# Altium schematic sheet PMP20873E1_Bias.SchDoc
size 431 x 279 mm; Date: Not shown in title block; ApprovedBy: Not shown in title block; CheckedBy: Not shown in title block; Author: Not shown in title block; CompanyName: Not shown in title block; DrawnBy: Eric Faraci; Engineer: Not shown in title block; Organization: Not shown in title block; Address1: Not shown in title block; Address2: Not shown in title block; Address3: Not shown in title block; Address4: Not shown in title block; DocumentNumber: 1; Revision: Use project parameter SCH_Rev; SheetNumber: 1; SheetTotal: 1; PageSetup: Record=PageOptions¦CenterHorizontal=True¦CenterVertical=True¦PrintScale=0.64¦XCorrection=1.00¦YCorrection=1.00¦PrintKind=0¦BorderSize=5000000¦LeftOffset=0¦BottomOffset=0¦Orientation=2¦PaperLength=1000¦PaperWidth=1000¦Scale=100¦PaperSource=15¦PrintQuality=600¦MediaType=1¦DitherType=10¦PaperKind=Letter¦PrintScaleMode=1
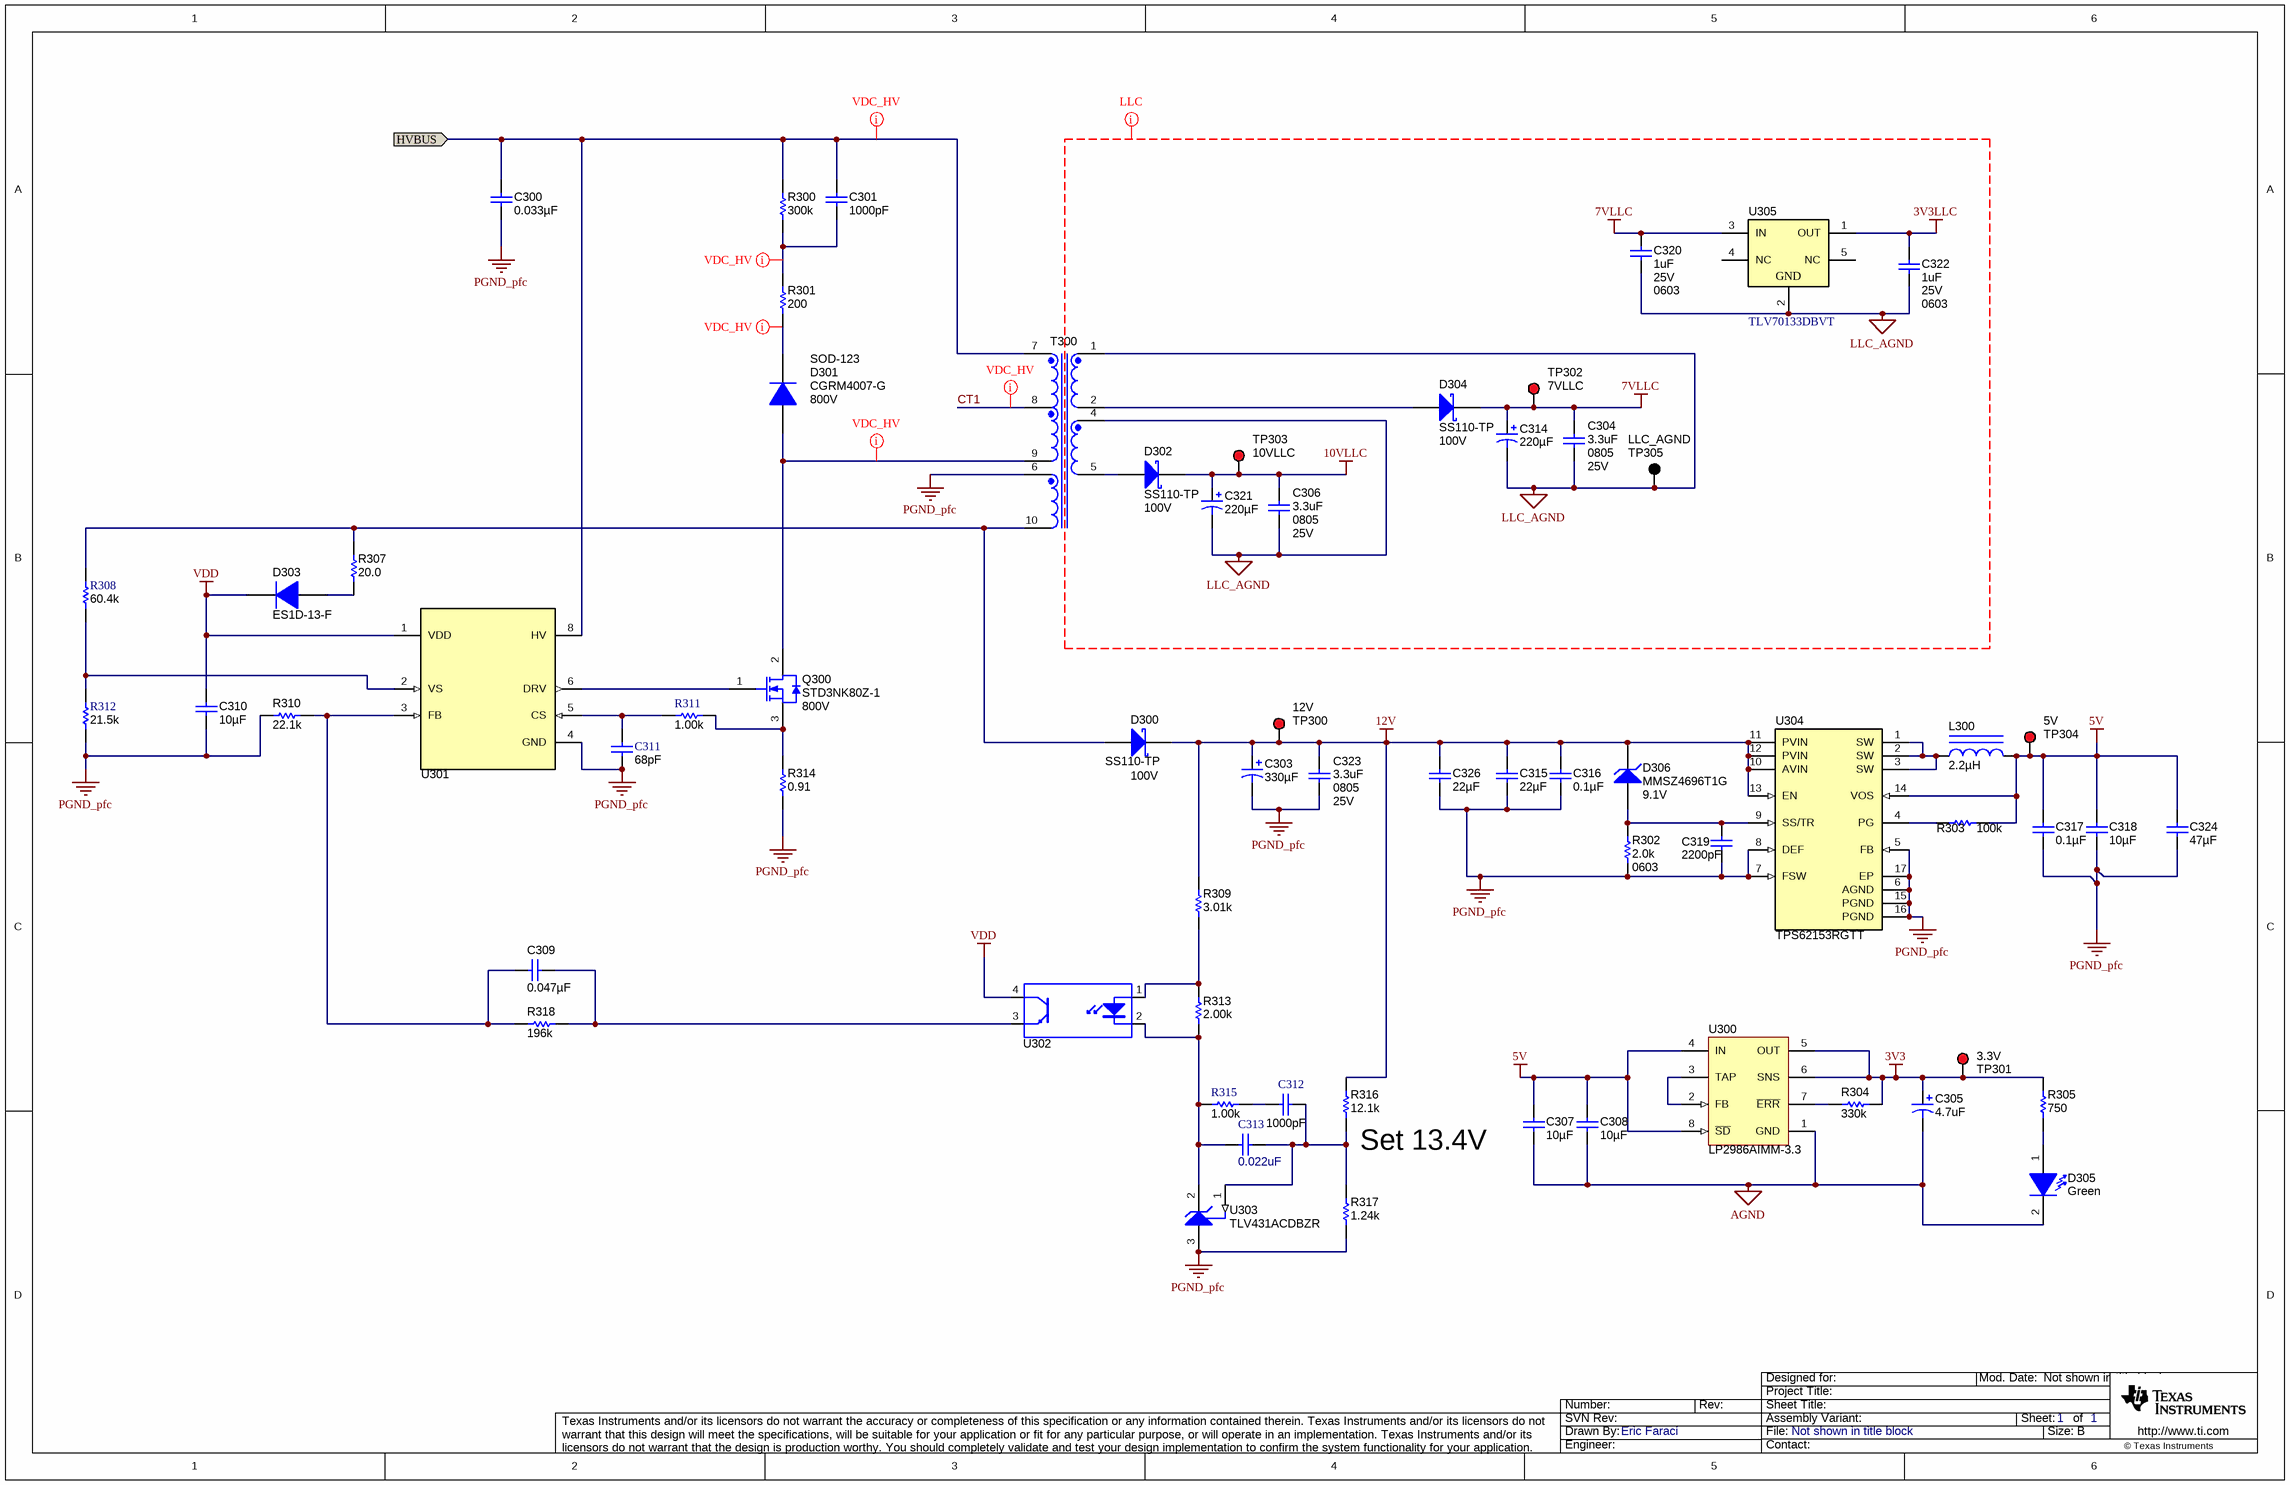
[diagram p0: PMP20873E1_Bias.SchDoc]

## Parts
C300  ValueDisplayed: 0.033µF  [1210]  (hidden comment: GRM32DR72J333KW01L)
C301  ValueDisplayed: 1000pF  [0805_HV]  (hidden comment: C2012X7R2E102K)
C303  ValueDisplayed: 330µF  [ZL_1000x1250]  (hidden comment: 25ZL330MEFC10X12.5)
C304  ValueDisplayed: 3.3uF  PackageReference: 0805  Value2: 25V  [0805_HV]  (hidden comment: GRM21BR71E335KA73L)
C305  ValueDisplayed: 4.7uF  [3528-21]  (hidden comment: 293D475X9010B2TE3)
C306  ValueDisplayed: 3.3uF  PackageReference: 0805  Value2: 25V  [0805_HV]  (hidden comment: GRM21BR71E335KA73L)
C307  ValueDisplayed: 10µF  [0805_HV]  (hidden comment: C0805C106K8PACTU)
C308  ValueDisplayed: 10µF  [0805_HV]  (hidden comment: C0805C106K8PACTU)
C309  ValueDisplayed: 0.047µF  [0805_HV]  (hidden comment: C0805C473K5RACTU)
C310  ValueDisplayed: 10µF  [1206]  (hidden comment: GRM31CR71E106KA12L)
C311  ValueDisplayed: 68pF  [0603]  (hidden comment: 06035A680JAT2A)
C312  ValueDisplayed: 1000pF  [0603]  (hidden comment: 06035A102KAT2A)
C313  ValueDisplayed: 0.022uF  [0603]  (hidden comment: C0603C223K3RACTU)
C314  ValueDisplayed: 220µF  [7361-38]  (hidden comment: TPSV227K016R0050)
C315  ValueDisplayed: 22µF  [1206]  (hidden comment: 1206YD226MAT2A)
C316  ValueDisplayed: 0.1µF  [0402]  (hidden comment: C1005X7R1H104K)
C317  ValueDisplayed: 0.1µF  [0402]  (hidden comment: C1005X7R1H104K)
C318  ValueDisplayed: 10µF  [0805_HV]  (hidden comment: GRM21BR71A106KE51L)
C319  ValueDisplayed: 2200pF  [0402]  (hidden comment: GRM155R71E222KA01D)
C320  ValueDisplayed: 1uF  Value2: 25V  [0603]  (hidden comment: C1608X7R1E105K080AB)
C321  ValueDisplayed: 220µF  [7361-38]  (hidden comment: TPSV227K016R0050)
C322  ValueDisplayed: 1uF  Value2: 25V  [0603]  (hidden comment: C1608X7R1E105K080AB)
C323  ValueDisplayed: 3.3uF  PackageReference: 0805  Value2: 25V  [0805_HV]  (hidden comment: GRM21BR71E335KA73L)
C324  ValueDisplayed: 47µF  [1210]  (hidden comment: 12106D476MAT2A)
C326  ValueDisplayed: 22µF  [1206]  (hidden comment: 1206YD226MAT2A)
D300  SS110-TP  value 100V  [SMA]
D301  CGRM4007-G  Value2: 800V  [SOD-123]
D302  SS110-TP  value 100V  [SMA]
D303  ES1D-13-F  [SMA]
D304  SS110-TP  value 100V  [SMA]
D305  value Green  [LG L29K_GREEN]  (hidden comment: LG L29K-G2J1-24-Z)
D306  MMSZ4696T1G  value 9.1V  [SOD-123]
L300  ValueDisplayed: 2.2µH  [SDR0403]  (hidden comment: SDR0403-2R2ML)
Q300  STD3NK80Z-1  value 800V  [IPAK]
R300  ValueDisplayed: 300k  [1206]  (hidden comment: RC1206FR-07300KL)
R301  ValueDisplayed: 200  [0805_HV]  (hidden comment: ERJ-6GEYJ201V)
R302  value 2.0k  [0603]  (hidden comment: CRCW06032K00JNEA)
R303  value 100k  [0402]  (hidden comment: CRCW0402100KFKED)
R304  ValueDisplayed: 330k  [0603]  (hidden comment: RG1608P-334-B-T5)
R305  ValueDisplayed: 750  [0603]  (hidden comment: RT0603DRE07750RL)
R307  ValueDisplayed: 20.0  [0603]  (hidden comment: RC0603FR-0720RL)
R308  value 60.4k  [0603]  (hidden comment: CRCW060360K4FKEA)
R309  ValueDisplayed: 3.01k  [0805_HV]  (hidden comment: CRCW08053K01FKEA)
R310  ValueDisplayed: 22.1k  [0805_HV]  (hidden comment: CRCW080522K1FKEA)
R311  value 1.00k  [0603]  (hidden comment: CRCW06031K00FKEA)
R312  value 21.5k  [0603]  (hidden comment: CRCW060321K5FKEA)
R313  ValueDisplayed: 2.00k  [0805_HV]  (hidden comment: CRCW08052K00FKEA)
R314  ValueDisplayed: 0.91  [0805_HV]  (hidden comment: CRM0805-FX-R910ELF)
R315  value 1.00k  [0603]  (hidden comment: CRCW06031K00FKEA)
R316  ValueDisplayed: 12.1k  [0805_HV]  (hidden comment: CRCW080512K1FKEA)
R317  ValueDisplayed: 1.24k  [0805_HV]  (hidden comment: CRCW08051K24FKEA)
R318  ValueDisplayed: 196k  [0805_HV]  (hidden comment: ERJ-6ENF1963V)
T300  750315894  [Wurth_750315894]  (value not drawn)
TP300  12V  [Keystone5000]
TP301  3.3V  [Keystone5000]
TP302  7VLLC  [Keystone5000]
TP303  10VLLC  [Keystone5000]
TP304  5V  [Keystone5000]
TP305  LLC_AGND  [Keystone5001]
U300  LP2986AIMM-3.3  [MUA08A_N]
U301  UCC28740DR  [D0007A_N]  (value not drawn)
U302  LTV-817S  [DIP254P762X350-4]  (value not drawn)
U303  TLV431ACDBZR  [DBZ0003A_N]
U304  TPS62153RGTT  [RGT0016C]
U305  TLV70133DBVT  [DBV0005A_N]

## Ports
HVBUS

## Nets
3V3: C305.1(+) R304.2 R305.2 TP301.1 U300.5(OUT) U300.6(SNS)
3V3LLC: C322.2 U305.1(OUT)
5V: C307.1 C308.1 C317.1 C318.2 C324.1 L300.2 R303.2 TP304.1 U300.4(IN) U300.8(~{SD}) U304.14(VOS)
7VLLC: C304.1 C314.1(+) C320.2 D304.1(K) TP302.1 U305.3(IN)
10VLLC: C306.1 C321.1(+) D302.1(K) TP303.1
12V: C303.1(+) C315.1 C316.1 C323.1 C326.1 D300.1(K) D306.1(K) R309.2 R316.2 TP300.1 U304.10(AVIN) U304.11(PVIN) U304.12(PVIN) U304.13(EN)
AGND: C305.2(-) C307.2 C308.2 D305.2(K) U300.1(GND)
LLC_AGND: C304.2 C306.2 C314.2(-) C320.1 C321.2(-) C322.1 T300.1 T300.4 TP305.1 U305.2(GND)
PGND_pfc: C300.2 C303.2(-) C310.2 C311.2 C315.2 C316.2 C317.2 C318.1 C319.2 C323.2 C324.2 C326.2 R302.2 R310.1 R312.1 R314.1 R317.1 T300.6 U301.4(GND) U303.3(ANODE) U304.5(FB) U304.6(AGND) U304.7(FSW) U304.8(DEF) U304.15(PGND) U304.16(PGND) U304.17(EP)
VDD: C310.1 D303.1(K) U301.1(VDD) U302.4(C)
CT1: T300.8
HVBUS: C300.1 C301.1 R300.2 T300.7 U301.8(HV) ; port HVBUS
NetC301_2: C301.2 R300.1 R301.2
NetC309_1: C309.1 R318.2 U302.3(E)
NetC309_2: C309.2 R310.2 R318.1 U301.3(FB)
NetC311_1: C311.1 R311.1 U301.5(CS)
NetC312_1: C312.1 C313.1 R316.1 R317.2 U303.1(REF)
NetC312_2: C312.2 R315.2
NetC313_2: C313.2 R313.1 R315.1 U302.2(K) U303.2(CATHODE)
NetC319_1: C319.1 D306.2(A) R302.1 U304.9(SS/TR)
NetD300_2: D300.2(A) R307.2 R308.2 T300.10
NetD301_1: D301.1(K) R301.1
NetD301_2: D301.2(A) Q300.2(D) T300.9
NetD302_2: D302.2(A) T300.5
NetD303_2: D303.2(A) R307.1
NetD304_2: D304.2(A) T300.2
NetD305_1: D305.1(A) R305.1
NetL300_1: L300.1 U304.1(SW) U304.2(SW) U304.3(SW)
NetQ300_1: Q300.1(G) U301.6(DRV)
NetQ300_3: Q300.3(S) R311.2 R314.2
NetR303_1: R303.1 U304.4(PG)
NetR304_1: R304.1 U300.7(~{ERR})
NetR308_1: R308.1 R312.2 U301.2(VS)
NetR309_1: R309.1 R313.2 U302.1(A)
NetU300_2: U300.2(FB) U300.3(TAP)

Not connected (* = marked no-connect by the designer): U305 4(NC) 5(NC)

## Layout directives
net class VDC_HV: CT1, HVBUS, NetC301_2, NetD301_1, NetD301_2
net class LLC: 3V3LLC, 7VLLC, 10VLLC, LLC_AGND

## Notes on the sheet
- (near R316) Set 13.4V

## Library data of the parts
C300 = GRM32DR72J333KW01L: CAP, CERM, 0.033 µF, 630 V, +/- 10%, X7R, 1210; Manufacturer: MuRata; Polarized: N; CompType: Capacitor; Value: 0.033uF; U/M: EA; Cap_F: 0.000000033; Tolerance_%: 10; Value1: Unknown; VDC_V: 630; Value2: 630V; TaMin_C: -55; TaMax_C: 125; AEC Category: Q200
C301 = C2012X7R2E102K: CAP, CERM, 1000 pF, 250 V, +/- 10%, X7R, 0805; Manufacturer: TDK; Polarized: N; CompType: Capacitor; Value: 1000pF; U/M: EA; Cap_F: 0.000000001; Tolerance_%: 10; ESR_ohm: 0.2815; Value1: 0.2815 ohm; VDC_V: 250; Value2: 250V; TaMin_C: -55; TaMax_C: 125; Cap_Case: 0805; AEC Category: Q200
C303 = 25ZL330MEFC10X12.5: CAP, AL, 330 µF, 25 V, +/- 20%, 0.053 ohm, TH; Manufacturer: Rubycon; Polarized: Y; CompType: Capacitor; Value: 330uF; U/M: EA; Cap_F: 0.00033; Tolerance_%: 20; VDC_V: 25; Value2: 25V; ESR_ohm: 0.053; IRMS_A: 1.03; TaMin_C: -40; TaMax_C: 105; Cap_Case: 10x12.5mm
C304 C306 C323 = GRM21BR71E335KA73L: CAP, CERM, 3.3uF, 25V, +/-10%, X7R, 0805; Manufacturer: MuRata; Polarized: N; CompType: Capacitor; U/M: EA; Cap_F: 0.0000033; Tolerance_%: 10; Value1: Unknown; VDC_V: 25; TaMin_C: -55; TaMax_C: 125
C305 = 293D475X9010B2TE3: CAP, TA, 4.7uF, 10V, +/-10%, 3.4 ohm, SMD; Manufacturer: Vishay-Sprague; Polarized: Y; CompType: Capacitor; U/M: EA; Cap_F: 0.0000047; Tolerance_%: 10; Value1: 3.4 ohm; ESR_Ohm: 3.4; IRMS_A: 0.16; TaMin_C: -55; TaMax_C: 125; Cap_Case: B
C307 C308 = C0805C106K8PACTU: CAP, CERM, 10 µF, 10 V, +/- 10%, X5R, 0805; Manufacturer: Kemet; Polarized: N; CompType: Capacitor; Value: 10uF; U/M: EA; Cap_F: 0.00001; Tolerance_%: 10; ESR_ohm: 0.003; Value1: 0.003 ohm; Value2: 10V; IRMS_A: 11.43; TaMin_C: -55; TaMax_C: 85; Cap_Case: 0805
C309 = C0805C473K5RACTU: CAP, CERM, 0.047 µF, 50 V, +/- 10%, X7R, 0805; Manufacturer: Kemet; Polarized: N; CompType: Capacitor; Value: 0.047uF; U/M: EA; Cap_F: 0.000000047; Tolerance_%: 10; ESR_ohm: 0.088; Value1: 0.088 ohm; VDC_V: 50; Value2: 50V; IRMS_A: 1.04; TaMin_C: -55; TaMax_C: 125; Cap_Case: 0805; AEC Category: Q200
C310 = GRM31CR71E106KA12L: CAP, CERM, 10 µF, 25 V, +/- 10%, X7R, 1206; Manufacturer: MuRata; Polarized: N; CompType: Capacitor; Value: 10uF; U/M: EA; Cap_F: 0.00001; Tolerance_%: 10; Value1: Unknown; VDC_V: 25; Value2: 25V; TaMin_C: -55; TaMax_C: 125; Cap_Case: 2220; AEC Category: Q200
C311 = 06035A680JAT2A: CAP, CERM, 68pF, 50V, +/-5%, C0G/NP0, 0603; Manufacturer: AVX; Polarized: N; CompType: Capacitor; U/M: EA; Cap_F: 0.000000000068; Tolerance_%: 5; ESR_Ohm: 0.144; Value1: 0.144 ohm; VDC_V: 50; TaMin_C: -55; TaMax_C: 125
C312 = 06035A102KAT2A: CAP, CERM, 1000pF, 50V, +/-10%, C0G/NP0, 0603; Manufacturer: AVX; Polarized: N; CompType: Capacitor; U/M: EA; Cap_F: 0.000000001; Tolerance_%: 10; ESR_Ohm: 0.048; Value1: 0.048 ohm; VDC_V: 50; TaMin_C: -55; TaMax_C: 125
C313 = C0603C223K3RACTU: CAP, CERM, 0.022uF, 25V, +/-10%, X7R, 0603; Manufacturer: Kemet; Polarized: N; CompType: Capacitor; U/M: EA; Cap_F: 0.000000022; Tolerance_%: 10; Value1: Unknown; VDC_V: 25; TaMin_C: -55; TaMax_C: 125
C314 C321 = TPSV227K016R0050: CAP, TA, 220 µF, 16 V, +/- 10%, 0.05 ohm, SMD; Manufacturer: AVX; Polarized: Y; CompType: Capacitor; Value: 220uF; U/M: EA; Cap_F: 0.00022; Tolerance_%: 10; VDC_V: 16; Value2: 16V; ESR_ohm: 0.05; IRMS_A: 2.012; TaMin_C: -55; TaMax_C: 125
C315 C326 = 1206YD226MAT2A: CAP, CERM, 22 µF, 16 V, +/- 20%, X5R, 1206; Manufacturer: AVX; Polarized: N; CompType: Capacitor; Value: 22uF; U/M: EA; Cap_F: 0.000022; Tolerance_%: 20; Value1: Unknown; VDC_V: 16; Value2: 16V; TaMin_C: -55; TaMax_C: 85; AEC Category: Q200
C316 C317 = C1005X7R1H104K: CAP, CERM, 0.1uF, 50V, +/-10%, C0G/NP0, 0402; Manufacturer: TDK; Polarized: N; CompType: Capacitor; U/M: EA; Cap_F: 0.0000001; Tolerance_%: 10; VDC_V: 50; TaMin_C: -55; TaMax_C: 125
C318 = GRM21BR71A106KE51L: CAP, CERM, 10uF, 10V, +/-10%, X7R, 0805; Manufacturer: MuRata; Polarized: N; CompType: Capacitor; U/M: EA; Cap_F: 0.00001; Tolerance_%: 10; ESR_Ohm: 0.003; Value1: 0.003 ohm; TaMin_C: -55; TaMax_C: 125; Cap_Case: 0805
C319 = GRM155R71E222KA01D: CAP, CERM, 2200pF, 25V, +10/%, X7R, 0402; Manufacturer: MuRata; Polarized: N; CompType: Capacitor; U/M: EA; Cap_F: 0.0000000022; Tolerance_%: 10; Value1: Unknown; VDC_V: 25; TaMin_C: -55; TaMax_C: 125
C320 C322 = C1608X7R1E105K080AB: CAP, CERM, 1uF, 25V, +/-10%, X7R, 0603; Manufacturer: TDK; Polarized: N; CompType: Capacitor; U/M: EA; Cap_F: 0.000001; Tolerance_%: 10; Value1: Unknown; VDC_V: 25; TaMin_C: -55; TaMax_C: 125
C324 = 12106D476MAT2A: CAP, CERM, 47 µF, 6.3 V, +/- 20%, X5R, 1210; Manufacturer: AVX; Polarized: N; CompType: Capacitor; Value: 47uF; U/M: EA; Cap_F: 0.000047; Tolerance_%: 20; Value1: Unknown; VDC_V: 6.3; Value2: 6.3V; TaMin_C: -55; TaMax_C: 85; AEC Category: Q200
D300 D302 D304 = 10BQ100TRPBF: Diode, Schottky, 100V, 1A, SMB; Manufacturer: International Rectifier; U/M: EA; Vf_V: 0.78; Value2: 0.78V; Io_A: 1; Vr_V: 100; TJmax_C: 175; RJC_CperW: 36
D301 = US1M-13-F: Diode, Ultrafast, 800V, 1A, SMA; Manufacturer: Diodes Inc.; Value: 1.7V; U/M: EA; Vf_V: 1.7; Io_A: 1; Vr_V: 800; TJmax_C: 150; RJC_CperW: 30
D303 = ES1D-13-F: Diode, Ultrafast, 200 V, 1 A, SMA; Manufacturer: Diodes Inc.; U/M: EA; Vf_V: 0.92; Value: 200V; Value1: 1A; Value2: 0.92V; Io_A: 1; Vr_V: 200; TJmax_C: 150; RJC_CperW: 25; AEC Category: Q101
D305 = LG L29K-G2J1-24-Z: LED, Green, SMD; Manufacturer: OSRAM; Vf_V: 1.7; Value2: 1.7V; Io_A: 0.002; Tjmax_C: 110; Value1: W; U/M: EA
D306 = MMSZ4696T1G: Diode, Zener, 9.1 V, 500 mW, SOD-123; Manufacturer: ON Semiconductor; SymbolCreator: a0412235; U/M: EA; Power_W: 0.5; Vz_V: 9.1; Value1: 0.5W; RJA_CperW: 340; AEC Category: Q101
L300 = SDR0403-2R2ML: Inductor, Drum Core, Ferrite, 2.2 µH, 2.6 A, 0.047 ohm, SMD; Manufacturer: Bourns; Value: 2.2uH; Ind_H: 2.2E-6; Imax_A: 2.6; Irms: 2.6A @ 40C rise; Isat: 3.77A @ 10% inductance drop; DCR_ohm: 0.047; Value2: 2.6A; AEC Category: Q200
Q300 = STD3NK80Z-1: MOSFET, N-CH, 800V, 2.5A, IPAK; Manufacturer: ST Microelectronics; Alternate Manufacturer: None; U/M: EA; ChType: N; VdsMax_V: 800; Value1: 4.5 ohm; Rdson45_Ohm: 4.5; Value2: 19 nC; QgTyp_nC: 19; Vgs_V: 30; IdsMax_A: 2.5
R300 = RC1206FR-07300KL: RES, 300 k, 1%, 0.25 W, 1206; Manufacturer: Yageo America; CompType: Resistor; Value: 300k; Res_ohm: 300000; Tolerance_%: 1; Power_W: 0.25; Value2: 0.25W; VDC_V: 200; TempCo: 100 ppm/C; U/M: EA; AEC Category: Q200
R301 = ERJ-6GEYJ201V: RES, 200, 5%, 0.125 W, 0805; Manufacturer: Panasonic; CompType: Resistor; Value: 200; Value_Code: 200R; Tolerance_%: 5; Power_W: 0.125; Value2: 0.125W; VDC_V: 150; TempCo: 200 ppm/C; EIA_Code: E24; U/M: EA; AEC Category: Q200
R302 = CRCW06032K00JNEA: RES, 2.0k ohm, 5%, 0.1W, 0603; Manufacturer: Vishay-Dale; CompType: Resistor; Res_ohm: 2000; Value_Code: 2k00; Tolerance_%: 5; Power_W: 0.1; VDC_V: 75; TempCo: 200 ppm/C; EIA_Code: E24; U/M: EA
R303 = CRCW0402100KFKED: RES, 100k ohm, 1%, 0.063W, 0402; Manufacturer: Vishay-Dale; Alternate PartNumber: Equivalent; Alternate Manufacturer: Any; CompType: Resistor; Res_ohm: 100000; Tolerance_%: 1; Power_W: 0.063; VDC_V: 50; TempCo: 100 ppm/C; EIA_Code: E96; U/M: EA
R304 = RG1608P-334-B-T5: RES, 330 k, 0.1%, 0.1 W, 0603; Manufacturer: Susumu Co Ltd; CompType: Resistor; Value: 330k; Res_ohm: 330000; Tolerance_%: 0.1; Value2: 0.1W; VDC_V: 75; TempCo: 25 ppm/C; U/M: EA; AEC Category: Q200
R305 = RT0603DRE07750RL: RES, 750, 0.5%, 0.1 W, 0603; Manufacturer: Yageo America; CompType: Resistor; Value: 750; Value_Code: 750R; Tolerance_%: 0.5; Power_W: 0.1; Value2: 0.1W; VDC_V: 75; TempCo: 50 ppm/C; EIA_Code: E192; U/M: EA; AEC Category: Q200
R307 = RC0603FR-0720RL: RES, 20.0, 1%, 0.1 W, 0603; Manufacturer: Yageo America; CompType: Resistor; Value: 20.0; Res_ohm: 20; Value_Code: 20R0; Tolerance_%: 1; Power_W: 0.1; Value2: 0.1W; VDC_V: 150; TempCo: 200 ppm/C; EIA_Code: E96; U/M: EA; AEC Category: Q200
R308 = CRCW060360K4FKEA: RES, 60.4k ohm, 1%, 0.1W, 0603; Manufacturer: Vishay-Dale; CompType: Resistor; Res_ohm: 60400; Value_Code: 60k4; Tolerance_%: 1; Power_W: 0.1; VDC_V: 75; TempCo: 100 ppm/C; EIA_Code: E96; U/M: EA
R309 = CRCW08053K01FKEA: RES, 3.01 k, 1%, 0.125 W, 0805; Manufacturer: Vishay-Dale; CompType: Resistor; Value: 3.01k; Res_ohm: 3010; Value_Code: 3k01; Tolerance_%: 1; Power_W: 0.125; Value2: 0.125W; VDC_V: 150; TempCo: 100 ppm/C; EIA_Code: E96; U/M: EA
R310 = CRCW080522K1FKEA: RES, 22.1 k, 1%, 0.125 W, 0805; Manufacturer: Vishay-Dale; CompType: Resistor; Value: 22.1k; Res_ohm: 22100; Value_Code: 22k1; Tolerance_%: 1; Power_W: 0.125; Value2: 0.125W; VDC_V: 150; TempCo: 100 ppm/C; EIA_Code: E96; U/M: EA
R311 R315 = CRCW06031K00FKEA: RES, 1.00k ohm, 1%, 0.1W, 0603; Manufacturer: Vishay-Dale; CompType: Resistor; Res_ohm: 1000; Value_Code: 1k00; Tolerance_%: 1; Power_W: 0.1; VDC_V: 75; TempCo: 100 ppm/C; EIA_Code: E96; U/M: EA
R312 = CRCW060321K5FKEA: RES, 21.5k ohm, 1%, 0.1W, 0603; Manufacturer: Vishay-Dale; CompType: Resistor; Res_ohm: 21500; Value_Code: 21k5; Tolerance_%: 1; Power_W: 0.1; VDC_V: 75; TempCo: 100 ppm/C; EIA_Code: E96; U/M: EA
R313 = CRCW08052K00FKEA: RES, 2.00 k, 1%, 0.125 W, 0805; Manufacturer: Vishay-Dale; CompType: Resistor; Value: 2.00k; Res_ohm: 2000; Value_Code: 2k00; Tolerance_%: 1; Power_W: 0.125; Value2: 0.125W; VDC_V: 150; TempCo: 100 ppm/C; EIA_Code: E96; U/M: EA
R314 = CRM0805-FX-R910ELF: RES, 0.91, 1%, 0.25 W, 0805; Manufacturer: Bourns; CompType: Resistor; Value: 0.91; Value_Code: R910; Tolerance_%: 1; Power_W: 0.25; Value2: 0.25W; VDC_V: 0; TempCo: 100 ppm/C; EIA_Code: E96; U/M: EA; AEC Category: Q200
R316 = CRCW080512K1FKEA: RES, 12.1 k, 1%, 0.125 W, 0805; Manufacturer: Vishay-Dale; CompType: Resistor; Value: 12.1k; Res_ohm: 12100; Value_Code: 12k1; Tolerance_%: 1; Power_W: 0.125; Value2: 0.125W; VDC_V: 150; TempCo: 100 ppm/C; EIA_Code: E96; U/M: EA; AEC Category: Q200
R317 = CRCW08051K24FKEA: RES, 1.24 k, 1%, 0.125 W, 0805; Manufacturer: Vishay-Dale; CompType: Resistor; Value: 1.24k; Res_ohm: 1240; Value_Code: 1k24; Tolerance_%: 1; Power_W: 0.125; Value2: 0.125W; VDC_V: 150; TempCo: 100 ppm/C; EIA_Code: E96; U/M: EA
R318 = ERJ-6ENF1963V: RES, 196 k, 1%, 0.125 W, 0805; Manufacturer: Panasonic; CompType: Resistor; Value: 196k; Res_ohm: 196000; Tolerance_%: 1; Power_W: 0.125; Value2: 0.125W; TempCo: 100 ppm/C; EIA_Code: E96; U/M: EA; AEC Category: Q200
T300 = 750315894: Transformer, 13 mH, TH; Manufacturer: Wurth Elektronik; SymbolCreator: Altium; Lp: 13000; DCR_ohm: 20.9; LeakageL: 200; Ns1toNp: 0.042; Ns2toNp: 0.035; Rs1: 0.045; Rs2: 0.4
TP300-TP304 = 5000: Test Point, Miniature, Red, TH; Manufacturer: Keystone; CompType: Test Point Loop; U/M: EA
TP305 = 5001: Test Point, Miniature, Black, TH; Manufacturer: Keystone; CompType: Test Point Loop; U/M: EA
U300 = LP2986AIMM-3.3: Micropower, 200 mA Ultra Low-Dropout Fixed or Adjustable Voltage Regulator, 8-pin Mini SOIC; Manufacturer: National Semiconductor; PackageTopMarking: ZXTT*L40A; PowerWise: N; CompType: LDO IC
U301 = UCC28740DR: Constant-Voltage, Constant-Current Flyback Controller Using Opto-Coupler Feedback, D0007A; Manufacturer: Texas Instruments; SymbolCreator: a0412235; CompType: IC; U/M: EA
U302 = LTV-817S: Optocoupler, 5 kV, 50-600% CTR, TH-4; Manufacturer: Lite-On; CTR_Min: 50% @ 5mA; CTR_Max: 600% @ 5mA; Voltage_Isolation_Vrms: 5000; tr_typ: 4us; tf_typ: 3us; U/M: EA
U303 = TLV431ACDBZR: Low Voltage Adjustable Precision Shunt Regulator, 39 ppm / degC, 15 mA, 0 to 70 degC, 3-pin SOT-23 (DBZ), Green (RoHS & no Sb/Br); Manufacturer: Texas Instruments; Alternate PartNumber: Equivalent; Iout/Iz(Max)(mA): 15; Min Iz for Regulation(uA): 80; Rating: Catalog; SubFamily: Shunt Voltage Reference; Temp Coeff(Max)(ppm/ degree C): 129; Temp Coeff(Typ)(ppm/ degree C): 39; VO Adj(Max)(V): 6; VO Adj(Min)(V): 1.24
U304 = TPS62153RGTT: Buck Step Down Regulator with 3 to 17 V Input and 5 V Output, -40 to 85 degC, 16-Pin QFN (RGT), Green (RoHS & no Sb/Br); Manufacturer: Texas Instruments; Alternate PartNumber: Equivalent; Duty Cycle(Max)(%): 100; Iout(Max)(A): 1; Iq(Typ)(mA): 0.017; Preset Vout(V): 5; Rating: Catalog; SubFamily: Step-Down Regulator; Switch Current Limit(Typ)(A): 1.7; Synchronous Rectification: TRUE; Vin(Max)(V): 17; Vin(Min)(V): 3
U305 = TLV70133DBVT: Single Output LDO, 150 mA, Fixed 3.3 V Output, 2.5 to 24 V Input, with Ultra-Low IQ, 5-pin SOT-23 (DBV), -40 to 85 degC, Green (RoHS & no Sb/Br); Manufacturer: Texas Instruments; Alternate PartNumber: Equivalent; Accuracy(%): 2; Fixed Output Options(V): 3.3; Iout(Max)(A): 0.15; Iq(Typ)(mA): 0.032; SubFamily: Single Channel LDO; Vdo(Typ)(mV): 400; Vin(Max)(V): 24; Vin(Min)(V): 2.5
